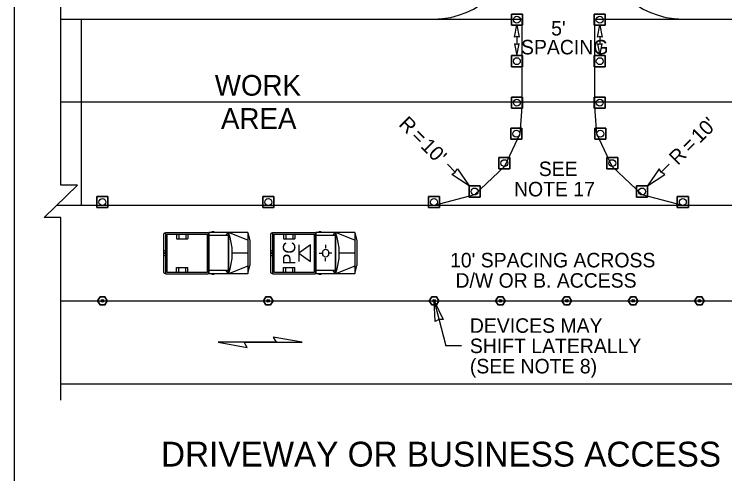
# Model space of a CAD drawing. Extents: x 99999.1 to 100095.7, y 99995 to 100010.7.
# Drawn here: x 100070.5 to 100073.928, y 100006.235 to 100008.454 of the extents above; entities that cross this region are included whole.
import ezdxf

# ---------------------------------------------------------------- set-up
doc = ezdxf.new("R2010")
doc.units = 0
for name, color, linetype in [('RD_ED_DrivewayEdge', 7, 'Continuous'), ('RD_ED_ShoulderPavedEdge', 7, 'Continuous'), ('RD_MK_LineEdgeWhite', 7, 'Continuous'), ('RD_MK_LineSkipCenter', 7, 'Continuous'), ('SH_DE_DetailHeading2Text', 7, 'Continuous'), ('TR_WZ_MotoristVehicle', 7, 'Continuous'), ('TR_WZ_PortableSignMountBlk-Wht', 7, 'Continuous'), ('TR_WZ_TrafficCone', 7, 'Continuous'), ('TR_WZ_TubularMarker', 7, 'Continuous'), ('TR_WZ_WorkAreaLabel', 7, 'Continuous'), ('TR_WZ_WorkZoneDetails', 7, 'Continuous'), ('TR_WZ_WorkZoneTextCurrent', 7, 'Continuous')]:
    doc.layers.add(name, color=color, linetype=linetype)

msp = doc.modelspace()

# ---------------------------------------------------------------- linework, layer by layer
at = {"layer": 'RD_ED_DrivewayEdge'}
for centre, start, end in [((100072.525, 100008.8304), 270, 0), ((100073.725, 100008.8304), 180, 270)]:
    msp.add_arc(centre, 0.4, start, end, dxfattribs=at)
at = {"layer": 'RD_ED_ShoulderPavedEdge'}
for p, q in [((100070.725, 100008.4305), (100072.525, 100008.4305)), ((100073.725, 100008.4305), (100075.525, 100008.4305)), ((100070.725, 100006.6704), (100075.525, 100006.6704))]:
    msp.add_line(p, q, dxfattribs=at)
at = {"layer": 'RD_MK_LineEdgeWhite'}
for p, q in [((100070.725, 100008.0305), (100075.525, 100008.0305)), ((100070.725, 100007.0704), (100075.525, 100007.0704))]:
    msp.add_line(p, q, dxfattribs=at)
at = {"layer": 'RD_MK_LineSkipCenter'}
msp.add_lwpolyline([(100075.5043, 100007.5305), (100070.7043, 100007.5305)], dxfattribs=at)
at = {"layer": 'TR_WZ_MotoristVehicle'}
for p, q in [((100071.2252, 100007.3972), (100071.2297, 100007.3972)), ((100071.2297, 100007.3972), (100071.2297, 100007.2037)), ((100071.2304, 100007.4005), (100071.4361, 100007.4005)), ((100071.2304, 100007.4005), (100071.2304, 100007.2005)), ((100071.4361, 100007.4005), (100071.4361, 100007.2005)), ((100071.4388, 100007.4005), (100071.4388, 100007.2005)), ((100071.6277, 100007.4005), (100071.4388, 100007.4005)), ((100071.4646, 100007.4033), (100071.4533, 100007.4033)), ((100071.5316, 100007.4005), (100071.5195, 100007.385)), ((100071.5316, 100007.4005), (100071.5316, 100007.2005)), ((100071.5333, 100007.4005), (100071.5333, 100007.2005)), ((100071.6277, 100007.3638), (100071.5333, 100007.4005)), ((100071.6277, 100007.4005), (100071.6277, 100007.2005)), ((100071.6277, 100007.4005), (100071.637, 100007.3601)), ((100071.7415, 100007.3972), (100071.7459, 100007.3972)), ((100071.7459, 100007.3972), (100071.7459, 100007.2037)), ((100071.7466, 100007.4005), (100071.9523, 100007.4005)), ((100071.7466, 100007.4005), (100071.7466, 100007.2005)), ((100071.9523, 100007.4005), (100071.9523, 100007.2005)), ((100071.9551, 100007.4005), (100071.9551, 100007.2005)), ((100072.144, 100007.4005), (100071.9551, 100007.4005)), ((100071.9809, 100007.4033), (100071.9695, 100007.4033)), ((100072.0478, 100007.4005), (100072.0358, 100007.385)), ((100072.0478, 100007.4005), (100072.0478, 100007.2005)), ((100072.0495, 100007.4005), (100072.0495, 100007.2005)), ((100072.144, 100007.3638), (100072.0495, 100007.4005)), ((100072.144, 100007.4005), (100072.144, 100007.2005)), ((100072.144, 100007.4005), (100072.1533, 100007.3601)), ((100071.2207, 100007.3911), (100071.2207, 100007.2098)), ((100071.2362, 100007.3925), (100071.2362, 100007.2084)), ((100071.2362, 100007.3925), (100071.4302, 100007.3925)), ((100071.2826, 100007.3925), (100071.2826, 100007.3695)), ((100071.2826, 100007.3695), (100071.3375, 100007.3695)), ((100071.2936, 100007.3925), (100071.2936, 100007.3695)), ((100071.3276, 100007.3925), (100071.3276, 100007.3695)), ((100071.3375, 100007.3925), (100071.3375, 100007.3695)), ((100071.4302, 100007.3925), (100071.4302, 100007.2084)), ((100071.5316, 100007.385), (100071.4388, 100007.385)), ((100071.737, 100007.3911), (100071.737, 100007.2098)), ((100071.7525, 100007.3925), (100071.7525, 100007.2084)), ((100071.7525, 100007.3925), (100071.9465, 100007.3925)), ((100071.7988, 100007.3925), (100071.7988, 100007.3695)), ((100071.7988, 100007.3695), (100071.8538, 100007.3695)), ((100071.8098, 100007.3925), (100071.8098, 100007.3695)), ((100071.8438, 100007.3925), (100071.8438, 100007.3695)), ((100071.8538, 100007.3925), (100071.8538, 100007.3695)), ((100071.9465, 100007.3925), (100071.9465, 100007.2084)), ((100072.0478, 100007.385), (100071.9551, 100007.385)), ((100071.637, 100007.3601), (100071.637, 100007.2408)), ((100072.0025, 100007.3401), (100072.0025, 100007.3239)), ((100072.1533, 100007.3601), (100072.1533, 100007.2408)), ((100071.2207, 100007.3145), (100071.2297, 100007.3108)), ((100071.2231, 100007.3005), (100071.2273, 100007.3005)), ((100071.2252, 100007.3033), (100071.2252, 100007.2976)), ((100071.6277, 100007.3005), (100071.5518, 100007.3005)), ((100071.737, 100007.3145), (100071.7459, 100007.3108)), ((100071.7394, 100007.3005), (100071.7435, 100007.3005)), ((100071.7415, 100007.3033), (100071.7415, 100007.2976)), ((100071.9716, 100007.2997), (100071.9865, 100007.3001)), ((100071.9884, 100007.3001), (100071.9884, 100007.3001)), ((100072.0326, 100007.3006), (100072.02, 100007.3005)), ((100072.144, 100007.3005), (100072.0681, 100007.3005)), ((100071.2207, 100007.2864), (100071.2297, 100007.2901)), ((100071.737, 100007.2864), (100071.7459, 100007.2901)), ((100072.0018, 100007.262), (100072.0021, 100007.277)), ((100071.2826, 100007.2084), (100071.2826, 100007.2314)), ((100071.2826, 100007.2314), (100071.3375, 100007.2314)), ((100071.2936, 100007.2084), (100071.2936, 100007.2314)), ((100071.3276, 100007.2084), (100071.3276, 100007.2314)), ((100071.3375, 100007.2084), (100071.3375, 100007.2314)), ((100071.6277, 100007.2371), (100071.5333, 100007.2005)), ((100071.6277, 100007.2005), (100071.637, 100007.2408)), ((100071.7988, 100007.2084), (100071.7988, 100007.2314)), ((100071.7988, 100007.2314), (100071.8538, 100007.2314)), ((100071.8098, 100007.2084), (100071.8098, 100007.2314)), ((100071.8438, 100007.2084), (100071.8438, 100007.2314)), ((100071.8538, 100007.2084), (100071.8538, 100007.2314)), ((100072.144, 100007.2371), (100072.0495, 100007.2005)), ((100072.144, 100007.2005), (100072.1533, 100007.2408)), ((100071.2252, 100007.2037), (100071.2297, 100007.2037)), ((100071.2304, 100007.2005), (100071.4361, 100007.2005)), ((100071.2362, 100007.2084), (100071.4302, 100007.2084)), ((100071.5316, 100007.216), (100071.4388, 100007.216)), ((100071.6277, 100007.2005), (100071.4388, 100007.2005)), ((100071.4646, 100007.1976), (100071.4533, 100007.1976)), ((100071.5216, 100007.216), (100071.5316, 100007.2005)), ((100071.7415, 100007.2037), (100071.7459, 100007.2037)), ((100071.7466, 100007.2005), (100071.9523, 100007.2005)), ((100071.7525, 100007.2084), (100071.9465, 100007.2084)), ((100072.0478, 100007.216), (100071.9551, 100007.216)), ((100072.144, 100007.2005), (100071.9551, 100007.2005)), ((100071.9809, 100007.1976), (100071.9695, 100007.1976)), ((100072.0379, 100007.216), (100072.0478, 100007.2005))]:
    msp.add_line(p, q, dxfattribs=at)
for centre, major_axis, start_param, end_param in [((100071.2252, 100007.3911), (0, 0.0061), 6.283185, 7.853982), ((100071.3983, 100007.3004), (0, 0.2099), 4.215852, 5.209111), ((100071.7415, 100007.3911), (0, 0.0061), 6.283185, 7.853982), ((100071.9146, 100007.3004), (0, 0.2099), 4.215852, 5.209111), ((100071.2252, 100007.2098), (0, -0.0061), 4.712389, 6.283185), ((100071.7415, 100007.2098), (0, -0.0061), 4.712389, 6.283185)]:
    msp.add_ellipse(centre, major_axis=major_axis, ratio=0.73155, start_param=start_param, end_param=end_param, dxfattribs=at)
for centre, major_axis in [((100071.2252, 100007.3005), (0, -0.00282)), ((100071.7415, 100007.3005), (0, -0.00282)), ((100072.0025, 100007.3005), (0, -0.0193))]:
    msp.add_ellipse(centre, major_axis=major_axis, ratio=0.73155, dxfattribs=at)
at = {"layer": 'TR_WZ_PortableSignMountBlk-Wht'}
msp.add_line((100071.8727, 100007.3404), (100071.8727, 100007.2604), dxfattribs=at)
msp.add_lwpolyline([(100071.8727, 100007.3004), (100071.9301, 100007.2604), (100071.9301, 100007.3404)], close=True, dxfattribs=at)
at = {"layer": 'TR_WZ_TrafficCone'}
for points in [[(100072.8984, 100008.4538), (100072.9517, 100008.4538), (100072.9517, 100008.4005), (100072.8984, 100008.4005), (100072.8984, 100008.4538)], [(100072.8984, 100008.4005), (100072.9517, 100008.4005), (100072.9517, 100008.4538), (100072.8984, 100008.4538), (100072.8984, 100008.4005)], [(100073.2983, 100008.4538), (100073.3516, 100008.4538), (100073.3516, 100008.4005), (100073.2983, 100008.4005), (100073.2983, 100008.4538)], [(100073.2983, 100008.4005), (100073.3516, 100008.4005), (100073.3516, 100008.4538), (100073.2983, 100008.4538), (100073.2983, 100008.4005)], [(100072.8984, 100008.2538), (100072.9517, 100008.2538), (100072.9517, 100008.2005), (100072.8984, 100008.2005), (100072.8984, 100008.2538)], [(100072.8984, 100008.2005), (100072.9517, 100008.2005), (100072.9517, 100008.2538), (100072.8984, 100008.2538), (100072.8984, 100008.2005)], [(100073.2983, 100008.2538), (100073.3516, 100008.2538), (100073.3516, 100008.2005), (100073.2983, 100008.2005), (100073.2983, 100008.2538)], [(100073.2983, 100008.2005), (100073.3516, 100008.2005), (100073.3516, 100008.2538), (100073.2983, 100008.2538), (100073.2983, 100008.2005)], [(100072.8984, 100008.0538), (100072.9517, 100008.0538), (100072.9517, 100008.0005), (100072.8984, 100008.0005), (100072.8984, 100008.0538)], [(100072.8984, 100008.0005), (100072.9517, 100008.0005), (100072.9517, 100008.0538), (100072.8984, 100008.0538), (100072.8984, 100008.0005)], [(100073.2983, 100008.0538), (100073.3516, 100008.0538), (100073.3516, 100008.0005), (100073.2983, 100008.0005), (100073.2983, 100008.0538)], [(100073.2983, 100008.0005), (100073.3516, 100008.0005), (100073.3516, 100008.0538), (100073.2983, 100008.0538), (100073.2983, 100008.0005)], [(100072.8956, 100007.9038), (100072.949, 100007.9038), (100072.949, 100007.8505), (100072.8956, 100007.8505), (100072.8956, 100007.9038)], [(100072.8956, 100007.8505), (100072.949, 100007.8505), (100072.949, 100007.9038), (100072.8956, 100007.9038), (100072.8956, 100007.8505)], [(100073.301, 100007.9038), (100073.3544, 100007.9038), (100073.3544, 100007.8505), (100073.301, 100007.8505), (100073.301, 100007.9038)], [(100073.301, 100007.8505), (100073.3544, 100007.8505), (100073.3544, 100007.9038), (100073.301, 100007.9038), (100073.301, 100007.8505)], [(100072.8381, 100007.7615), (100072.8914, 100007.7615), (100072.8914, 100007.7082), (100072.8381, 100007.7082), (100072.8381, 100007.7615)], [(100072.8381, 100007.7082), (100072.8914, 100007.7082), (100072.8914, 100007.7615), (100072.8381, 100007.7615), (100072.8381, 100007.7082)], [(100073.3586, 100007.7615), (100073.4119, 100007.7615), (100073.4119, 100007.7082), (100073.3586, 100007.7082), (100073.3586, 100007.7615)], [(100073.3586, 100007.7082), (100073.4119, 100007.7082), (100073.4119, 100007.7615), (100073.3586, 100007.7615), (100073.3586, 100007.7082)], [(100072.6944, 100007.6247), (100072.7477, 100007.6247), (100072.7477, 100007.5714), (100072.6944, 100007.5714), (100072.6944, 100007.6247)], [(100072.6944, 100007.5714), (100072.7477, 100007.5714), (100072.7477, 100007.6247), (100072.6944, 100007.6247), (100072.6944, 100007.5714)], [(100073.5023, 100007.6247), (100073.5556, 100007.6247), (100073.5556, 100007.5714), (100073.5023, 100007.5714), (100073.5023, 100007.6247)], [(100073.5023, 100007.5714), (100073.5556, 100007.5714), (100073.5556, 100007.6247), (100073.5023, 100007.6247), (100073.5023, 100007.5714)], [(100070.899, 100007.5738), (100070.9524, 100007.5738), (100070.9524, 100007.5205), (100070.899, 100007.5205), (100070.899, 100007.5738)], [(100070.899, 100007.5205), (100070.9524, 100007.5205), (100070.9524, 100007.5738), (100070.899, 100007.5738), (100070.899, 100007.5205)], [(100071.699, 100007.5738), (100071.7524, 100007.5738), (100071.7524, 100007.5205), (100071.699, 100007.5205), (100071.699, 100007.5738)], [(100071.699, 100007.5205), (100071.7524, 100007.5205), (100071.7524, 100007.5738), (100071.699, 100007.5738), (100071.699, 100007.5205)], [(100072.499, 100007.5738), (100072.5524, 100007.5738), (100072.5524, 100007.5205), (100072.499, 100007.5205), (100072.499, 100007.5738)], [(100072.499, 100007.5205), (100072.5524, 100007.5205), (100072.5524, 100007.5738), (100072.499, 100007.5738), (100072.499, 100007.5205)], [(100073.699, 100007.5738), (100073.7524, 100007.5738), (100073.7524, 100007.5205), (100073.699, 100007.5205), (100073.699, 100007.5738)], [(100073.699, 100007.5205), (100073.7524, 100007.5205), (100073.7524, 100007.5738), (100073.699, 100007.5738), (100073.699, 100007.5205)]]:
    msp.add_lwpolyline(points, dxfattribs=at)
for centre in [(100072.925, 100008.4271), (100073.325, 100008.4271), (100072.925, 100008.2271), (100073.325, 100008.2271), (100072.925, 100008.0271), (100073.325, 100008.0271), (100072.9223, 100007.8771), (100073.3277, 100007.8771), (100072.8648, 100007.7349), (100073.3852, 100007.7349), (100072.721, 100007.598), (100073.529, 100007.598), (100070.9257, 100007.5471), (100071.7257, 100007.5471), (100072.5257, 100007.5471), (100073.7257, 100007.5471)]:
    msp.add_circle(centre, 0.0167, dxfattribs=at)
at = {"layer": 'TR_WZ_TubularMarker'}
for points in [[(100070.9026, 100007.0704), (100070.9142, 100007.0904), (100070.9373, 100007.0904), (100070.9488, 100007.0704), (100070.9373, 100007.0504), (100070.9142, 100007.0504)], [(100071.7026, 100007.0704), (100071.7141, 100007.0904), (100071.7372, 100007.0904), (100071.7488, 100007.0704), (100071.7372, 100007.0504), (100071.7141, 100007.0504)], [(100072.5026, 100007.0704), (100072.5141, 100007.0904), (100072.5372, 100007.0904), (100072.5488, 100007.0704), (100072.5372, 100007.0504), (100072.5141, 100007.0504)], [(100072.8226, 100007.0704), (100072.8341, 100007.0904), (100072.8572, 100007.0904), (100072.8688, 100007.0704), (100072.8572, 100007.0504), (100072.8341, 100007.0504)], [(100073.1426, 100007.0704), (100073.1541, 100007.0904), (100073.1772, 100007.0904), (100073.1888, 100007.0704), (100073.1772, 100007.0504), (100073.1541, 100007.0504)], [(100073.4626, 100007.0704), (100073.4741, 100007.0904), (100073.4972, 100007.0904), (100073.5088, 100007.0704), (100073.4972, 100007.0504), (100073.4741, 100007.0504)], [(100073.7826, 100007.0704), (100073.7941, 100007.0904), (100073.8172, 100007.0904), (100073.8288, 100007.0704), (100073.8172, 100007.0504), (100073.7941, 100007.0504)]]:
    msp.add_lwpolyline(points, close=True, dxfattribs=at)
for points in [[(100070.9142, 100007.0504), (100070.9373, 100007.0504), (100070.9488, 100007.0704), (100070.9373, 100007.0904), (100070.9142, 100007.0904), (100070.9026, 100007.0704), (100070.9142, 100007.0504)], [(100071.7141, 100007.0504), (100071.7372, 100007.0504), (100071.7488, 100007.0704), (100071.7372, 100007.0904), (100071.7141, 100007.0904), (100071.7026, 100007.0704), (100071.7141, 100007.0504)], [(100072.5141, 100007.0504), (100072.5372, 100007.0504), (100072.5488, 100007.0704), (100072.5372, 100007.0904), (100072.5141, 100007.0904), (100072.5026, 100007.0704), (100072.5141, 100007.0504)], [(100072.8341, 100007.0504), (100072.8572, 100007.0504), (100072.8688, 100007.0704), (100072.8572, 100007.0904), (100072.8341, 100007.0904), (100072.8226, 100007.0704), (100072.8341, 100007.0504)], [(100073.1541, 100007.0504), (100073.1772, 100007.0504), (100073.1888, 100007.0704), (100073.1772, 100007.0904), (100073.1541, 100007.0904), (100073.1426, 100007.0704), (100073.1541, 100007.0504)], [(100073.4741, 100007.0504), (100073.4972, 100007.0504), (100073.5088, 100007.0704), (100073.4972, 100007.0904), (100073.4741, 100007.0904), (100073.4626, 100007.0704), (100073.4741, 100007.0504)], [(100073.7941, 100007.0504), (100073.8172, 100007.0504), (100073.8288, 100007.0704), (100073.8172, 100007.0904), (100073.7941, 100007.0904), (100073.7826, 100007.0704), (100073.7941, 100007.0504)]]:
    msp.add_lwpolyline(points, dxfattribs=at)
for centre in [(100070.9257, 100007.0704), (100071.7257, 100007.0704), (100072.5257, 100007.0704), (100072.8457, 100007.0704), (100073.1657, 100007.0704), (100073.4857, 100007.0704), (100073.8057, 100007.0704)]:
    msp.add_circle(centre, 0.00667, dxfattribs=at)
at = {"layer": 'TR_WZ_WorkZoneDetails'}
for p, q in [((100070.5, 100010.275), (100070.5, 100001.6859)), ((100072.9251, 100008.3459), (100072.9251, 100008.3083)), ((100073.325, 100008.3459), (100073.325, 100008.3083)), ((100072.6281, 100007.691), (100072.5897, 100007.7294)), ((100073.6219, 100007.691), (100073.6603, 100007.7294)), ((100072.5257, 100007.0704), (100072.5821, 100006.853)), ((100071.7642, 100006.8704), (100071.6098, 100006.8704)), ((100071.6098, 100006.8704), (100071.7642, 100006.8704)), ((100072.6583, 100006.853), (100072.5821, 100006.853))]:
    msp.add_line(p, q, dxfattribs=at)
msp.add_lwpolyline([(100070.725, 100006.5904), (100070.725, 100007.473), (100070.645, 100007.473), (100070.805, 100007.6279), (100070.725, 100007.6279), (100070.725, 100008.5105)], dxfattribs=at)
for points in [[(100072.9483, 100008.4305), (100072.9483, 100008.2071), (100072.9483, 100008.0071), (100072.939, 100007.8771), (100072.939, 100007.8771), (100072.939, 100007.8771), (100072.8648, 100007.7182), (100072.8648, 100007.7182), (100072.8648, 100007.7182), (100072.721, 100007.5814), (100072.5257, 100007.5305), (100071.529, 100007.5305), (100070.949, 100007.5305), (100070.825, 100007.5305), (100070.825, 100008.4305)], [(100075.425, 100008.4305), (100075.425, 100008.0305), (100075.425, 100007.5305), (100074.501, 100007.5305), (100074.501, 100007.5305), (100074.501, 100007.5305), (100073.7257, 100007.5305), (100073.7257, 100007.5305), (100073.7257, 100007.5305), (100073.529, 100007.5814), (100073.3852, 100007.7182), (100073.311, 100007.8771), (100073.3017, 100008.0071), (100073.3017, 100008.2071), (100073.3017, 100008.4305)], [(100072.925, 100008.4005), (100072.9363, 100008.3433), (100072.925, 100008.3459), (100072.9138, 100008.3433)], [(100073.325, 100008.4005), (100073.3362, 100008.3433), (100073.325, 100008.3459), (100073.3137, 100008.3433)], [(100072.9251, 100008.2538), (100072.9363, 100008.3109), (100072.9251, 100008.3083), (100072.9139, 100008.3109)], [(100073.325, 100008.2538), (100073.3362, 100008.3109), (100073.325, 100008.3083), (100073.3138, 100008.3109)], [(100072.6944, 100007.6247), (100072.6113, 100007.6806), (100072.6281, 100007.691), (100072.6385, 100007.7079)], [(100073.5556, 100007.6247), (100073.6387, 100007.6806), (100073.6219, 100007.691), (100073.6115, 100007.7079)], [(100072.5257, 100007.0704), (100072.569, 100006.9801), (100072.5492, 100006.9797), (100072.5316, 100006.9705)], [(100071.8899, 100006.8704), (100071.7499, 100006.8951), (100071.7642, 100006.8704)], [(100071.4841, 100006.8704), (100071.6241, 100006.8458), (100071.6098, 100006.8704)]]:
    msp.add_lwpolyline(points, close=True, dxfattribs=at)

# ---------------------------------------------------------------- texts
at = {"layer": 'SH_DE_DetailHeading2Text'}
msp.add_text('DRIVEWAY OR BUSINESS ACCESS DETAIL', height=0.12, rotation=360, dxfattribs=at).set_placement((100071.2082, 100006.2704))
at = {"layer": 'TR_WZ_MotoristVehicle'}
msp.add_text('PC', height=0.06, rotation=90, dxfattribs=at).set_placement((100071.8563, 100007.2444))
at = {"layer": 'TR_WZ_WorkAreaLabel'}
for s, p in [('WORK', (100071.4678, 100008.0605)), ('AREA', (100071.4974, 100007.9004))]:
    msp.add_text(s, height=0.1, dxfattribs=at).set_placement(p)
at = {"layer": 'TR_WZ_WorkZoneTextCurrent'}
for s, p in [("5'", (100073.0904, 100008.3509)), ('SPACING', (100072.945, 100008.2599)), ('SEE', (100073.0308, 100007.6725)), ('NOTE 17', (100072.9113, 100007.5745)), ("10' SPACING ACROSS", (100072.6026, 100007.2318)), ('D/W OR B. ACCESS', (100072.6288, 100007.1338)), ('DEVICES MAY', (100072.6983, 100006.916)), ('SHIFT LATERALLY', (100072.6983, 100006.818)), ('(SEE NOTE 8)', (100072.6983, 100006.72))]:
    msp.add_text(s, height=0.07, dxfattribs=at).set_placement(p)
for s, rotation, p in [('R', 315, (100072.3509, 100007.9186)), ("10'", 45, (100073.8075, 100007.8271)), ('=', 315, (100072.4101, 100007.8595)), ("10'", 315, (100072.457, 100007.8126)), ('=', 45, (100073.7606, 100007.7802)), ('R', 45, (100073.7015, 100007.7211))]:
    msp.add_text(s, height=0.07, rotation=rotation, dxfattribs=at).set_placement(p)

doc.saveas('drawing.dxf')
